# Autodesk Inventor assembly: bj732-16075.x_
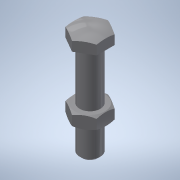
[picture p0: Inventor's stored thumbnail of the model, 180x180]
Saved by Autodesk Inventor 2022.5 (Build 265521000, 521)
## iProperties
Part Number: bj732-16075.x_
Material: 一般
Document SubType Name: Assembly
Designer: ImaoCorp
Sending System: SOLIDWORKS 2017-2017317
MC: AMD64
MC_MODEL: Intel64 Family 6 Model 60 Stepping 3, GenuineIntel
OS: Windows_NT
FRU: Parasolid Version 29.0, build 201,  4-17-2017
FORMAT: text
GUISE: transmit
KEY: bj732-16075
FILE: bj732-16075.x_t
DATE: Fri Mar 15 10:10:19 2019
Author: ImaoCorp
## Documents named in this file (3)
- X:\14_SW2022-Inv2022\00_全2023-1023新製品(TCC)まで\b\bj732-16075\BJ732-16075.iam
- X:\14_SW2022-Inv2022\00_全2023-1023新製品(TCC)まで\b\bj732-16075\bj732-16075_01.ipt
- X:\14_SW2022-Inv2022\00_全2023-1023新製品(TCC)まで\b\bj732-16075\bj732-16075_02.ipt
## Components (2 placed, 2 different names)
1. bj732-16075_01
2. bj732-16075_02
